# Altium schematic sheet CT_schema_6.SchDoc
size 577 x 363 mm
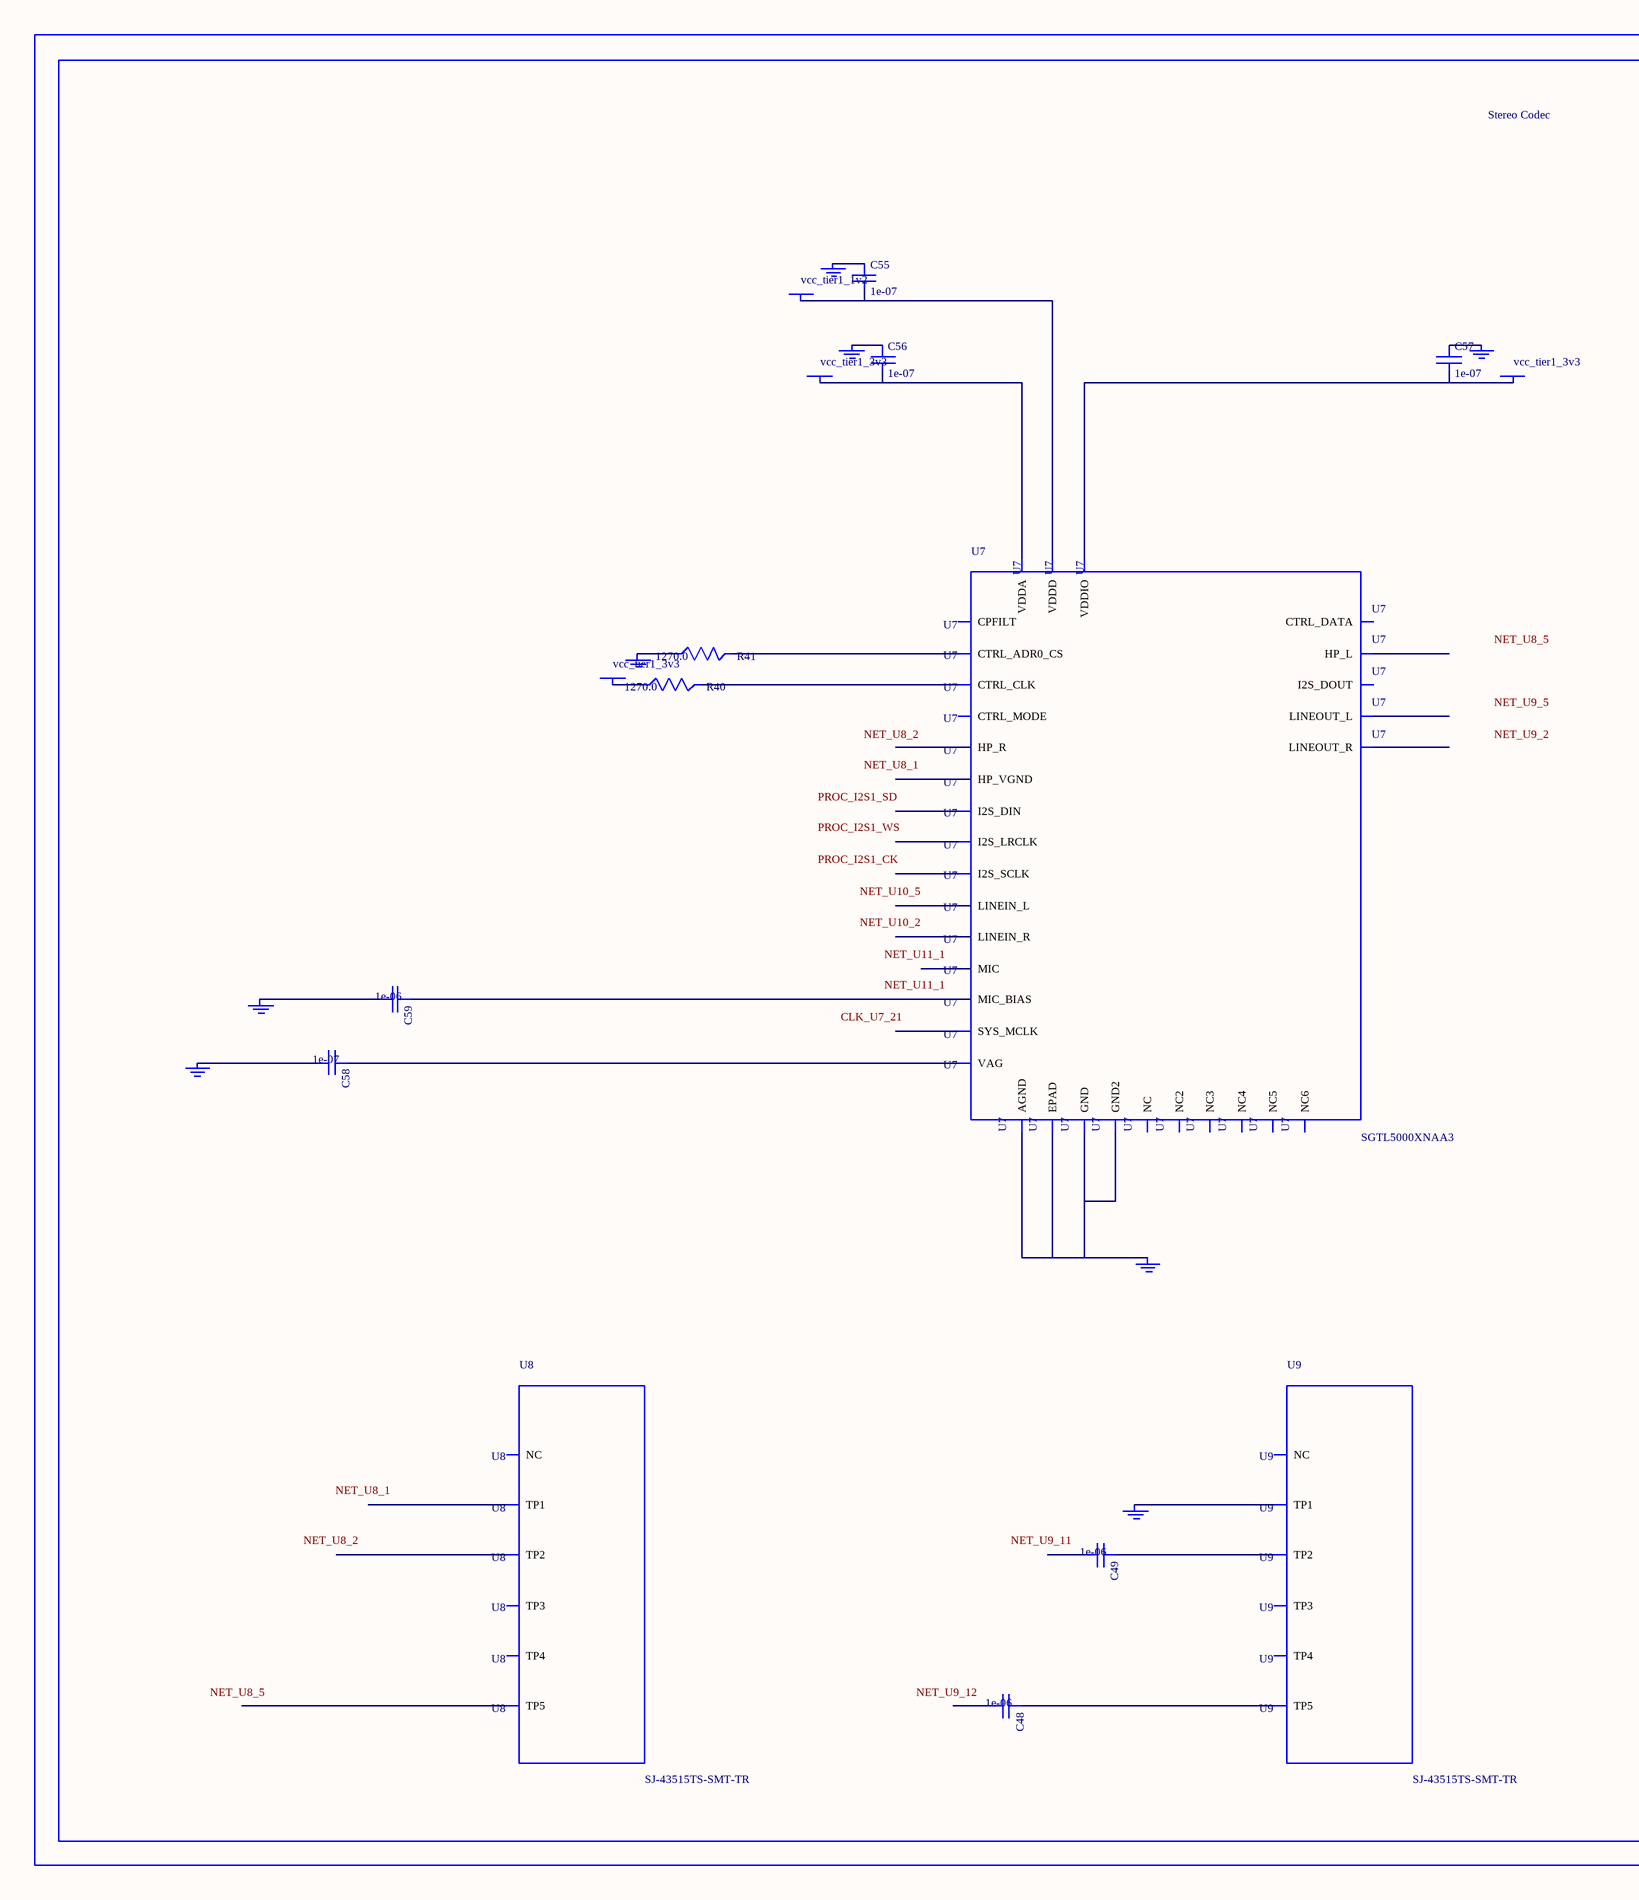
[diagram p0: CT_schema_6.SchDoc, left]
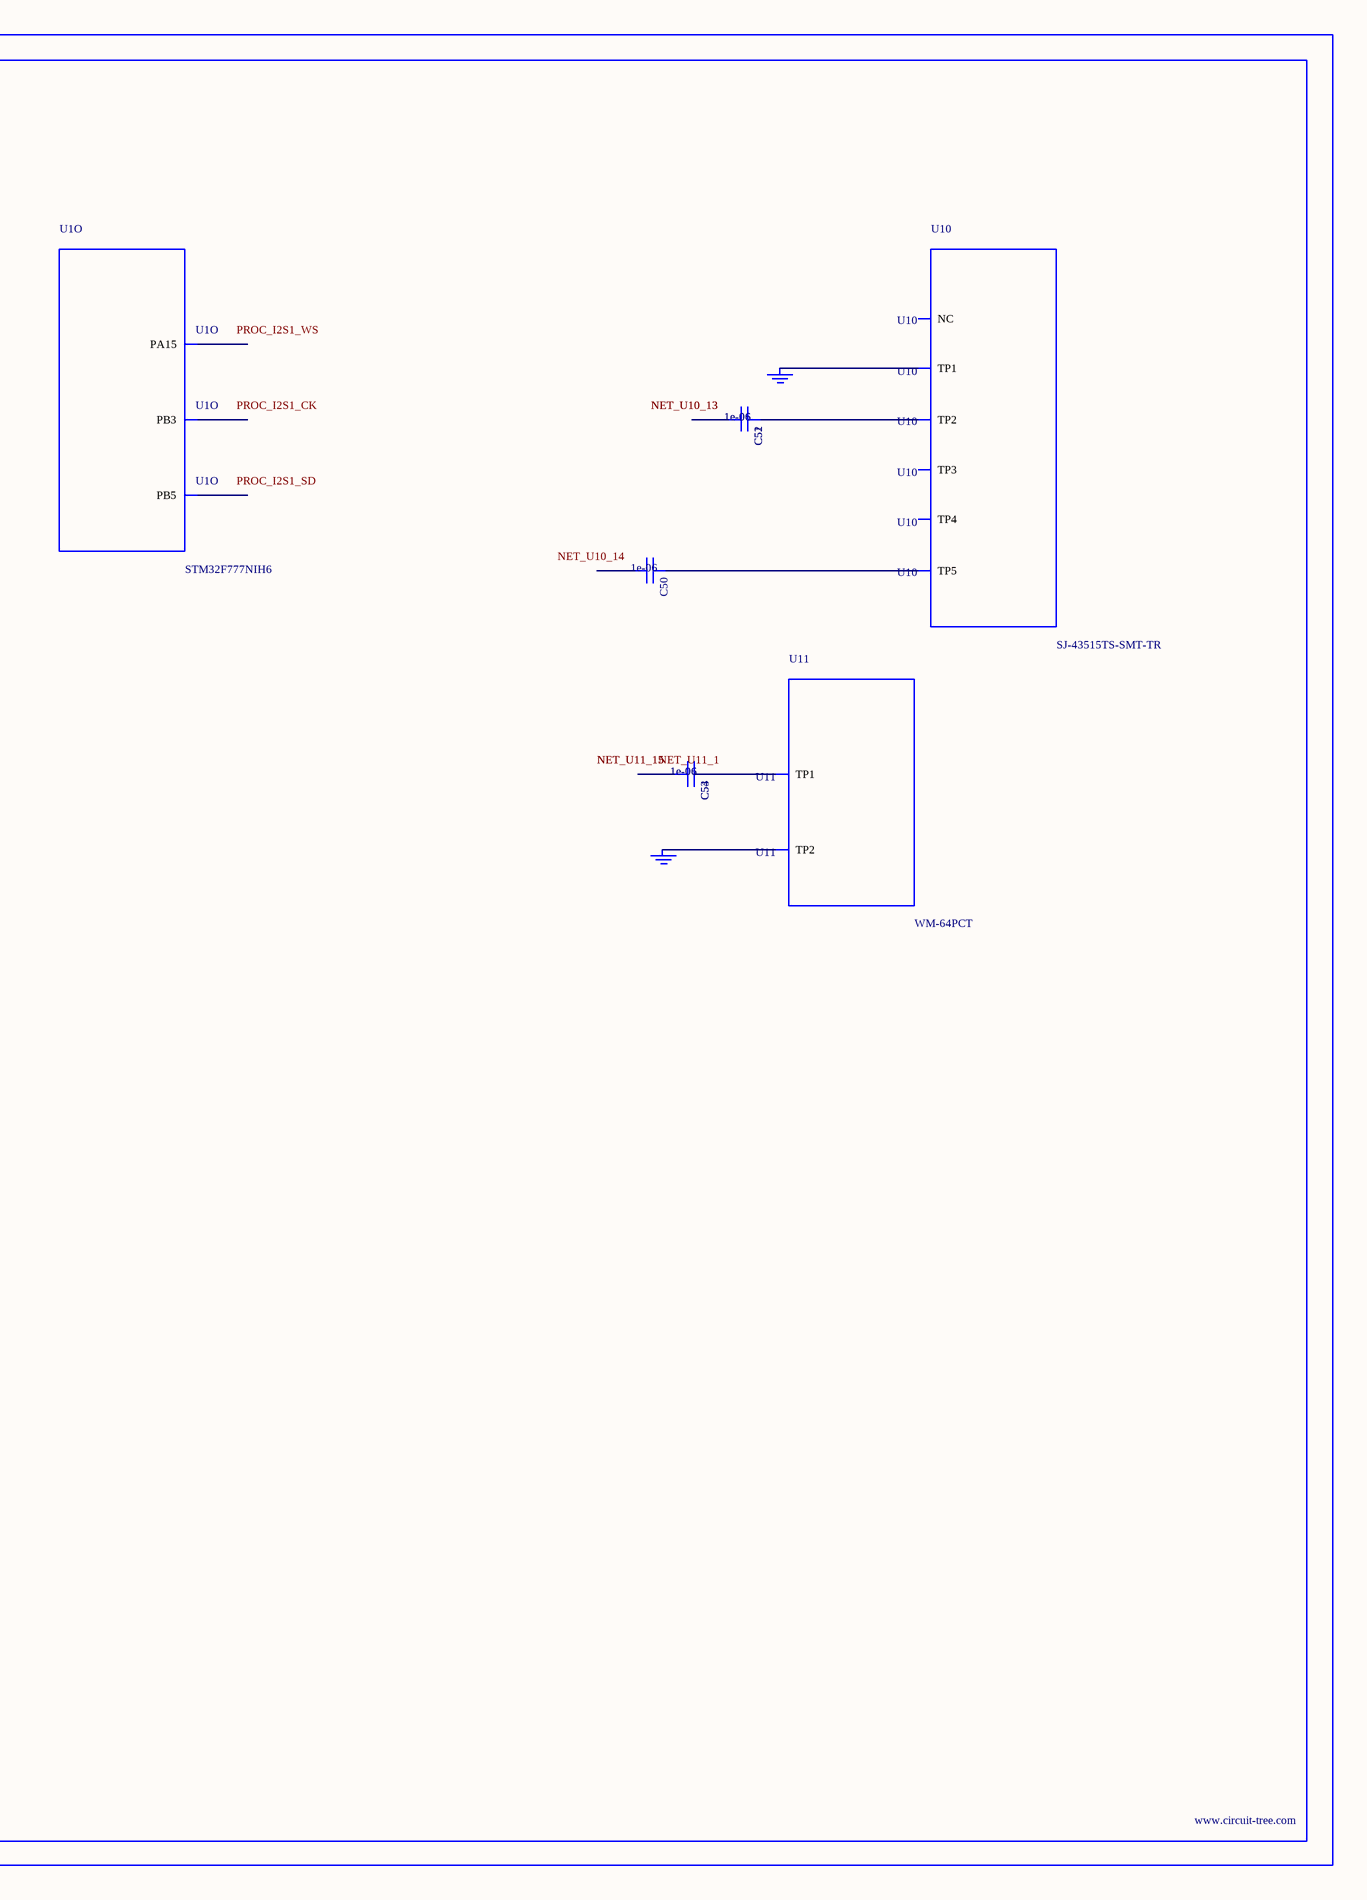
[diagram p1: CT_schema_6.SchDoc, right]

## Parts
BORDER5  (no value)
C48  1e-06  [C0603]
C49  1e-06  [C0603]
C50  1e-06  [C0603]
C51  1e-06  [C0603]
C52  1e-06  [C0603]
C53  1e-06  [C0603]
C54  1e-06  [C0603]
C55  1e-07  [C0402]
C56  1e-07  [C0402]
C57  1e-07  [C0402]
C58  1e-07  [C0402]
C59  1e-06  [C0603]
GND_INSTANCE_5_0  (no value)
GND_INSTANCE_5_1  (no value)
GND_INSTANCE_5_2  (no value)
GND_INSTANCE_5_3  (no value)
GND_INSTANCE_5_4  (no value)
GND_INSTANCE_5_5  (no value)
GND_INSTANCE_5_6  (no value)
GND_INSTANCE_5_7  (no value)
GND_INSTANCE_5_8  (no value)
GND_INSTANCE_5_9  (no value)
GND_INSTANCE_5_10  (no value)
POWER_INSTANCE_5_0  vcc_tier1_3v3
POWER_INSTANCE_5_1  vcc_tier1_3v3
POWER_INSTANCE_5_2  vcc_tier1_3v3
POWER_INSTANCE_5_3  vcc_tier1_1v2
R40  1270.0  [R0603]
R41  1270.0  [R0603]
U1  STM32F777NIH6  [TFBGA216]  (part O of 15)
U7  SGTL5000XNAA3  [QFN-32]
U8  SJ-43515TS-SMT-TR  [SJ-43515TS-SMT-TR]
U9  SJ-43515TS-SMT-TR  [SJ-43515TS-SMT-TR]
U10  SJ-43515TS-SMT-TR  [SJ-43515TS-SMT-TR]
U11  WM-64PCT  [WM-64PC]

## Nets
NetC48_1: C48.1 U9.5(TP5)
NetC49_1: C49.1 U9.2(TP2)
NetC50_1: C50.1 U10.5(TP5)
NetC51_1: C51.1 C52.1 U10.2(TP2)
NetC51_2: C51.2 C52.2
NetC53_1: C53.1 C54.1 U11.1(TP1)
NetC53_2: C53.2 C54.2
NetC55_1: C55.1 GND_INSTANCE_5_5.0(GND)
NetC55_2: C55.2 POWER_INSTANCE_5_3.0(PWR) U7.30(VDDD)
NetC56_1: C56.1 GND_INSTANCE_5_1.0(GND)
NetC56_2: C56.2 POWER_INSTANCE_5_0.0(PWR) U7.5(VDDA)
NetC57_1: C57.1 GND_INSTANCE_5_4.0(GND)
NetC57_2: C57.2 POWER_INSTANCE_5_1.0(PWR) U7.20(VDDIO)
NetC58_1: C58.1 U7.10(VAG)
NetC58_2: C58.2 GND_INSTANCE_5_2.0(GND)
NetC59_1: C59.1 U7.16(MIC_BIAS)
NetC59_2: C59.2 GND_INSTANCE_5_3.0(GND)
NetGND_INSTANCE_5_0_0: GND_INSTANCE_5_0.0(GND) U7.1(GND) U7.3(GND2) U7.7(AGND) U7.EXP(EPAD)
NetGND_INSTANCE_5_6_0: GND_INSTANCE_5_6.0(GND) R41.1
NetGND_INSTANCE_5_7_0: GND_INSTANCE_5_7.0(GND) U9.1(TP1)
NetGND_INSTANCE_5_8_0: GND_INSTANCE_5_8.0(GND) GND_INSTANCE_5_9.0(GND) U10.1(TP1)
NetGND_INSTANCE_5_10_0: GND_INSTANCE_5_10.0(GND) U11.2(TP2)
NetPOWER_INSTANCE_5_2_0: POWER_INSTANCE_5_2.0(PWR) R40.1
NetR40_2: R40.2 U7.29(CTRL_CLK)
NetR41_2: R41.2 U7.31(CTRL_ADR0_CS)

Not connected (* = marked no-connect by the designer): C48 2; C49 2; C50 2; U1 A8(PB5) A10(PB3) A13(PA15); U7 2(HP_R) 4(HP_VGND) 6(HP_L) 8(NC) 9(NC2) 11(LINEOUT_R) 12(LINEOUT_L) 13(LINEIN_R) 14(LINEIN_L) 15(MIC) 17(NC3) 18(CPFILT) 19(NC4) 21(SYS_MCLK) 22(NC5) 23(I2S_LRCLK) 24(I2S_SCLK) 25(I2S_DOUT) 26(I2S_DIN) 27(CTRL_DATA) 28(NC6) 32(CTRL_MODE); U8 1(TP1) 2(TP2) 3(TP3) 4(TP4) 5(TP5) 6(NC); U9 3(TP3) 4(TP4) 6(NC); U10 3(TP3) 4(TP4) 6(NC)

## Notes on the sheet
- Labels drawn without touching a wire or pin: CLK_U7_21, NET_U8_1, NET_U8_2, NET_U8_5, NET_U9_2, NET_U9_5, NET_U9_11, NET_U9_12, NET_U10_2, NET_U10_5, NET_U10_14, NET_U11_1, PROC_I2S1_CK, PROC_I2S1_SD, PROC_I2S1_WS

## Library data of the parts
BORDER5 = BORDER_PAGE5
C48-C54 C59 = C0603C105K3RACTU
C55-C58 = C0402C104K3RACTU
GND_INSTANCE_5_0-GND_INSTANCE_5_10 = GND
POWER_INSTANCE_5_0-POWER_INSTANCE_5_3 = PWR
R40 R41 = RC0603FR-071K27L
